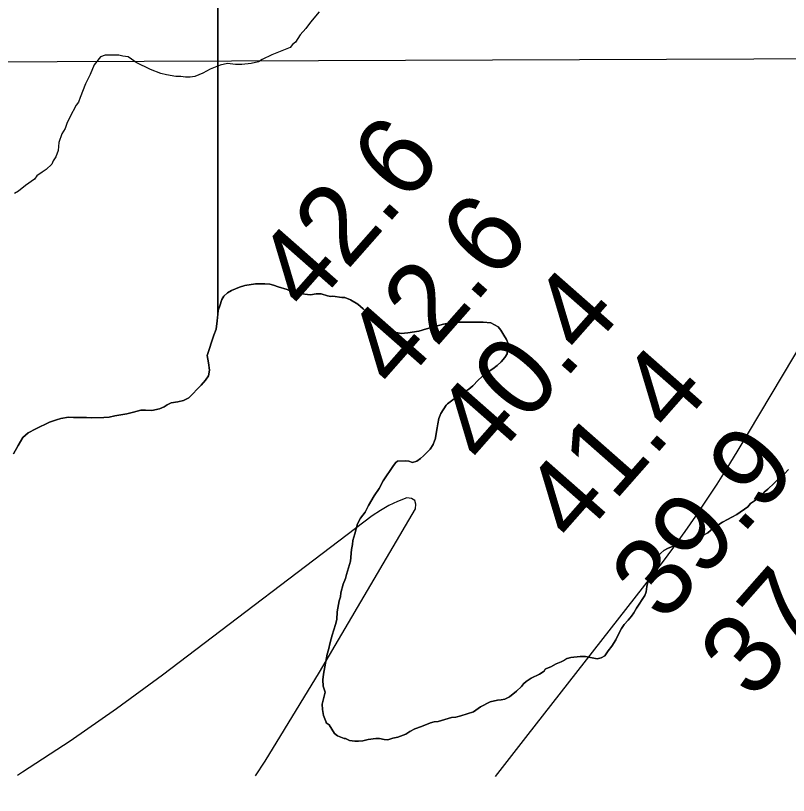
# Model space of a CAD drawing. Extents: x 3172297 to 3210190, y 958463 to 983887.
# Drawn here: x 3191237 to 3191893, y 963866 to 964528 of the extents above; entities that cross this region are included whole.
import ezdxf

# ---------------------------------------------------------------- set-up
doc = ezdxf.new("R2010")
doc.units = 0
for name, color, linetype in [('V-RIVR-RANG', 7, 'Continuous'), ('V-SITE-VEGE', 7, 'Continuous'), ('V-TOPO-BNDY', 7, 'Continuous'), ('V-TOPO-MAJR', 7, 'Continuous'), ('V-TOPO-SHOR', 7, 'Continuous'), ('V-WETL-SWMP', 7, 'Continuous')]:
    doc.layers.add(name, color=color, linetype=linetype)

msp = doc.modelspace()

# ---------------------------------------------------------------- linework, layer by layer
at = {"layer": 'V-SITE-VEGE'}
for p, q in [((3191409.01, 965103.6), (3191409.01, 964274.09)), ((3191409.01, 964274.09), (3191409.01, 965103.6)), ((3191427.47, 964297.52), (3191431.95, 964298.91)), ((3191431.95, 964298.91), (3191440.9, 964300.32)), ((3191440.9, 964300.32), (3191448.82, 964300.35)), ((3191448.82, 964300.35), (3191453.3, 964300.02)), ((3191453.3, 964300.02), (3191456.4, 964299.34)), ((3191456.4, 964299.34), (3191460.19, 964297.97)), ((3191414.06, 964289.9), (3191417.16, 964292.67)), ((3191417.16, 964292.67), (3191420.59, 964294.74)), ((3191420.59, 964294.74), (3191427.47, 964297.52)), ((3191460.19, 964297.97), (3191467.78, 964295.59)), ((3191467.78, 964295.59), (3191470.88, 964293.88)), ((3191470.88, 964293.88), (3191474.33, 964292.85)), ((3191474.33, 964292.85), (3191477.78, 964292.17)), ((3191410.65, 964281.63), (3191412.35, 964287.14)), ((3191412.35, 964287.14), (3191414.06, 964289.9)), ((3191477.78, 964292.17), (3191487.77, 964291.18)), ((3191487.77, 964291.18), (3191492.59, 964291.88)), ((3191492.59, 964291.88), (3191496.72, 964291.89)), ((3191496.72, 964291.89), (3191502.24, 964290.19)), ((3191502.24, 964290.19), (3191505, 964289.51)), ((3191505, 964289.51), (3191506.72, 964289.86)), ((3191506.72, 964289.86), (3191514.3, 964288.85)), ((3191514.3, 964288.85), (3191516.71, 964288.86)), ((3191516.71, 964288.86), (3191521.54, 964286.81)), ((3191521.54, 964286.81), (3191527.75, 964283.04)), ((3191409.28, 964277.83), (3191410.65, 964281.63)), ((3191527.75, 964283.04), (3191532.24, 964279.27)), ((3191532.24, 964279.27), (3191539.16, 964271.71)), ((3191408.62, 964268.87), (3191409.01, 964274.09)), ((3191409.01, 964274.09), (3191409.28, 964277.83)), ((3191407.61, 964261.98), (3191408.62, 964268.87)), ((3191539.16, 964271.71), (3191539.85, 964270.33)), ((3191539.85, 964270.33), (3191544.34, 964265.87)), ((3191544.34, 964265.87), (3191548.49, 964262.44)), ((3191586.03, 964262.22), (3191600.48, 964266.05)), ((3191600.48, 964266.05), (3191607.71, 964267.45)), ((3191607.71, 964267.45), (3191610.81, 964267.81)), ((3191610.81, 964267.81), (3191634.23, 964267.89)), ((3191634.23, 964267.89), (3191640.78, 964267.22)), ((3191640.78, 964267.22), (3191646.99, 964263.79)), ((3191405.56, 964256.81), (3191407.61, 964261.98)), ((3191548.49, 964262.44), (3191549.52, 964261.76)), ((3191549.52, 964261.76), (3191551.59, 964260.73)), ((3191551.59, 964260.73), (3191556.07, 964260.05)), ((3191556.07, 964260.05), (3191564.69, 964258.36)), ((3191570.2, 964258.72), (3191579.49, 964260.13)), ((3191579.49, 964260.13), (3191586.03, 964262.22)), ((3191646.99, 964263.79), (3191649.07, 964261.04)), ((3191649.07, 964261.04), (3191651.84, 964256.92)), ((3191400.1, 964239.57), (3191405.56, 964256.81)), ((3191564.69, 964258.36), (3191570.2, 964258.72)), ((3191651.84, 964256.92), (3191653.92, 964253.14)), ((3191653.92, 964253.14), (3191655.31, 964249.7)), ((3191655.31, 964249.7), (3191654.65, 964241.08)), ((3191401.16, 964233.37), (3191400.1, 964239.57)), ((3191654.65, 964241.08), (3191652.59, 964237.98)), ((3191401.87, 964227.17), (3191401.16, 964233.37)), ((3191649.5, 964234.18), (3191646.07, 964231.07)), ((3191652.59, 964237.98), (3191649.5, 964234.18)), ((3191401.19, 964222.35), (3191401.87, 964227.17)), ((3191642.29, 964228.3), (3191636.1, 964224.15)), ((3191646.07, 964231.07), (3191642.29, 964228.3)), ((3191398.45, 964218.55), (3191401.19, 964222.35)), ((3191636.1, 964224.15), (3191629.92, 964218.61)), ((3191384.38, 964203.7), (3191395.02, 964214.41)), ((3191395.02, 964214.41), (3191398.45, 964218.55)), ((3191625.46, 964213.78), (3191622.02, 964211.01)), ((3191629.92, 964218.61), (3191625.46, 964213.78)), ((3191614.11, 964206.16), (3191603.8, 964198.55)), ((3191616.86, 964207.55), (3191614.11, 964206.16)), ((3191622.02, 964211.01), (3191616.86, 964207.55)), ((3191369.58, 964199.51), (3191375.09, 964200.22)), ((3191375.09, 964200.22), (3191379.91, 964201.27)), ((3191379.91, 964201.27), (3191384.38, 964203.7)), ((3191337.57, 964191.49), (3191343.77, 964193.23)), ((3191343.77, 964193.23), (3191347.56, 964193.24)), ((3191347.56, 964193.24), (3191353.07, 964192.92)), ((3191353.07, 964192.92), (3191359.61, 964194.32)), ((3191359.61, 964194.32), (3191363.39, 964196.05)), ((3191363.39, 964196.05), (3191366.14, 964197.78)), ((3191366.14, 964197.78), (3191369.58, 964199.51)), ((3191602.77, 964197.52), (3191598.32, 964190.27)), ((3191603.8, 964198.55), (3191602.77, 964197.52)), ((3191275.94, 964186.12), (3191282.48, 964187.17)), ((3191282.48, 964187.17), (3191286.61, 964186.85)), ((3191286.61, 964186.85), (3191297.63, 964186.88)), ((3191297.63, 964186.88), (3191301.77, 964186.55)), ((3191301.77, 964186.55), (3191312.44, 964186.93)), ((3191312.44, 964186.93), (3191316.92, 964187.29)), ((3191316.92, 964187.29), (3191321.74, 964188.34)), ((3191321.74, 964188.34), (3191331.72, 964190.09)), ((3191331.72, 964190.09), (3191337.57, 964191.49)), ((3191598.32, 964190.27), (3191596.61, 964186.13)), ((3191254.61, 964177.44), (3191266.3, 964182.99)), ((3191266.3, 964182.99), (3191272.15, 964185.08)), ((3191272.15, 964185.08), (3191275.94, 964186.12)), ((3191595.59, 964181.65), (3191595.26, 964178.2)), ((3191596.61, 964186.13), (3191595.59, 964181.65)), ((3191243.61, 964169.83), (3191248.07, 964173.97)), ((3191248.07, 964173.97), (3191254.61, 964177.44)), ((3191595.26, 964178.2), (3191593.57, 964168.21)), ((3191239.5, 964163.27), (3191243.61, 964169.83)), ((3191593.23, 964167.86), (3191591.86, 964164.07)), ((3191593.57, 964168.21), (3191593.23, 964167.86)), ((3191235.73, 964156.02), (3191239.5, 964163.27)), ((3191589.12, 964159.93), (3191583.63, 964154.4)), ((3191591.86, 964164.07), (3191589.12, 964159.93)), ((3191583.63, 964154.4), (3191580.88, 964151.98)), ((3191560.22, 964148.81), (3191558.16, 964146.05)), ((3191561.6, 964149.85), (3191560.22, 964148.81)), ((3191568.14, 964150.21), (3191561.6, 964149.85)), ((3191571.24, 964149.88), (3191568.14, 964150.21)), ((3191574.35, 964148.86), (3191571.24, 964149.88)), ((3191577.79, 964149.9), (3191574.35, 964148.86)), ((3191580.88, 964151.98), (3191577.79, 964149.9)), ((3191558.16, 964146.05), (3191549.25, 964133.28)), ((3191889.54, 964138.86), (3191893.32, 964142.66)), ((3191880.96, 964131.25), (3191885.42, 964135.4)), ((3191885.42, 964135.4), (3191889.54, 964138.86)), ((3191545.83, 964126.72), (3191541.71, 964120.51)), ((3191549.25, 964133.28), (3191545.83, 964126.72)), ((3191875.8, 964126.07), (3191880.96, 964131.25)), ((3191541.71, 964120.51), (3191536.92, 964112.23)), ((3191865.16, 964116.73), (3191872.71, 964123.65)), ((3191872.71, 964123.65), (3191875.8, 964126.07)), ((3191858.63, 964111.2), (3191861.03, 964113.97)), ((3191861.03, 964113.97), (3191865.16, 964116.73)), ((3191536.92, 964112.23), (3191534.18, 964106.7)), ((3191849.35, 964104.63), (3191858.63, 964111.2)), ((3191530.06, 964101.53), (3191527.67, 964096.7)), ((3191534.18, 964106.7), (3191530.06, 964101.53)), ((3191837.32, 964098.05), (3191841.45, 964100.47)), ((3191841.45, 964100.47), (3191845.23, 964102.21)), ((3191845.23, 964102.21), (3191849.35, 964104.63)), ((3191527.67, 964096.7), (3191525.29, 964088.08)), ((3191829.41, 964092.85), (3191837.32, 964098.05)), ((3191525.29, 964088.08), (3191523.58, 964082.56)), ((3191820.48, 964086.62), (3191824.95, 964089.05)), ((3191824.95, 964089.05), (3191829.41, 964092.85)), ((3191523.58, 964082.56), (3191523.25, 964079.11)), ((3191790.55, 964075.85), (3191802.93, 964080.71)), ((3191802.93, 964080.71), (3191805.68, 964082.1)), ((3191805.68, 964082.1), (3191809.47, 964083.14)), ((3191809.47, 964083.14), (3191820.48, 964086.62)), ((3191522.58, 964074.98), (3191521.57, 964064.99)), ((3191523.25, 964079.11), (3191522.58, 964074.98)), ((3191782.3, 964069.62), (3191787.45, 964074.12)), ((3191787.45, 964074.12), (3191790.55, 964075.85)), ((3191780.25, 964064.79), (3191780.93, 964067.55)), ((3191780.93, 964067.55), (3191782.3, 964069.62)), ((3191521.57, 964064.99), (3191518.16, 964053.61)), ((3191779.58, 964059.97), (3191780.25, 964064.79)), ((3191775.12, 964051.69), (3191776.5, 964054.45)), ((3191776.5, 964054.45), (3191779.58, 964059.97)), ((3191517.49, 964050.16), (3191515.44, 964045.33)), ((3191518.16, 964053.61), (3191517.49, 964050.16)), ((3191773.08, 964043.42), (3191775.12, 964051.69)), ((3191515.44, 964045.33), (3191513.39, 964038.09)), ((3191772.41, 964038.93), (3191773.08, 964043.42)), ((3191513.06, 964034.65), (3191512.04, 964031.2)), ((3191513.39, 964038.09), (3191513.06, 964034.65)), ((3191764.19, 964025.13), (3191771.39, 964035.83)), ((3191771.39, 964035.83), (3191772.41, 964038.93)), ((3191511.36, 964028.1), (3191510.35, 964021.9)), ((3191512.04, 964031.2), (3191511.36, 964028.1)), ((3191510.35, 964021.9), (3191510.02, 964015.35)), ((3191760.08, 964018.23), (3191762.14, 964020.99)), ((3191762.14, 964020.99), (3191764.19, 964025.13)), ((3191510.02, 964015.35), (3191509, 964011.21)), ((3191753.9, 964011.32), (3191757.33, 964014.78)), ((3191757.33, 964014.78), (3191760.08, 964018.23)), ((3191509, 964011.21), (3191505.93, 964002.25)), ((3191749.45, 964004.07), (3191751.5, 964007.87)), ((3191751.5, 964007.87), (3191753.9, 964011.32)), ((3191505.93, 964002.25), (3191504.23, 963996.04)), ((3191746.71, 963998.21), (3191749.45, 964004.07)), ((3191504.23, 963996.04), (3191502.87, 963989.84)), ((3191743.28, 963992.69), (3191746.71, 963998.21)), ((3191502.87, 963989.84), (3191501.85, 963986.04)), ((3191737.45, 963984.74), (3191740.2, 963988.89)), ((3191740.2, 963988.89), (3191743.28, 963992.69)), ((3191501.85, 963986.04), (3191498.81, 963969.16)), ((3191700.27, 963979.46), (3191705.43, 963982.23)), ((3191705.43, 963982.23), (3191708.53, 963983.27)), ((3191708.53, 963983.27), (3191716.45, 963983.99)), ((3191716.45, 963983.99), (3191720.92, 963984)), ((3191720.92, 963984), (3191730.92, 963981.97)), ((3191730.92, 963981.97), (3191734.36, 963983.01)), ((3191734.36, 963983.01), (3191737.45, 963984.74)), ((3191687.89, 963973.91), (3191691.68, 963975.29)), ((3191691.68, 963975.29), (3191696.14, 963977.72)), ((3191696.14, 963977.72), (3191700.27, 963979.46)), ((3191498.81, 963969.16), (3191498.13, 963964.33)), ((3191674.83, 963965.59), (3191682.05, 963969.06)), ((3191682.05, 963969.06), (3191685.83, 963971.49)), ((3191685.83, 963971.49), (3191686.86, 963973.21)), ((3191686.86, 963973.21), (3191687.89, 963973.91)), ((3191498.13, 963964.33), (3191498.5, 963958.82)), ((3191668.3, 963960.75), (3191670.7, 963962.83)), ((3191670.7, 963962.83), (3191674.83, 963965.59)), ((3191498.5, 963958.82), (3191500.23, 963953.66)), ((3191662.46, 963954.53), (3191666.58, 963958.68)), ((3191666.58, 963958.68), (3191668.3, 963960.75)), ((3191500.23, 963953.66), (3191497.51, 963943.67)), ((3191652.5, 963947.96), (3191656.62, 963949.69)), ((3191656.62, 963949.69), (3191662.46, 963954.53)), ((3191497.51, 963943.67), (3191497.87, 963939.18)), ((3191631.85, 963941.34), (3191640.1, 963945.5)), ((3191640.1, 963945.5), (3191646.3, 963946.9)), ((3191646.3, 963946.9), (3191649.4, 963947.26)), ((3191649.4, 963947.26), (3191652.5, 963947.96)), ((3191497.87, 963939.18), (3191498.58, 963934.02)), ((3191615.34, 963933.71), (3191626.01, 963937.19)), ((3191626.01, 963937.19), (3191631.85, 963941.34)), ((3191498.58, 963934.02), (3191501.01, 963928.18)), ((3191501.01, 963928.18), (3191501.01, 963927.83)), ((3191589.53, 963927.78), (3191592.62, 963928.47)), ((3191592.62, 963928.47), (3191596.07, 963928.83)), ((3191596.07, 963928.83), (3191607.43, 963932.31)), ((3191607.43, 963932.31), (3191610.87, 963932.66)), ((3191610.87, 963932.66), (3191615.34, 963933.71)), ((3191501.01, 963927.83), (3191503.42, 963926.12)), ((3191503.42, 963926.12), (3191507.93, 963918.55)), ((3191571.99, 963920.48), (3191576.11, 963922.56)), ((3191576.11, 963922.56), (3191581.96, 963924.65)), ((3191581.96, 963924.65), (3191589.53, 963927.78)), ((3191507.93, 963918.55), (3191510.69, 963916.84)), ((3191510.69, 963916.84), (3191516.21, 963914.45)), ((3191557.54, 963914.58), (3191561.67, 963915.63)), ((3191561.67, 963915.63), (3191568.55, 963918.06)), ((3191568.55, 963918.06), (3191571.99, 963920.48)), ((3191516.21, 963914.45), (3191517.24, 963914.45)), ((3191517.24, 963914.45), (3191520.69, 963912.74)), ((3191520.69, 963912.74), (3191525.17, 963912.06)), ((3191525.17, 963912.06), (3191528.27, 963912.08)), ((3191528.27, 963912.08), (3191532.06, 963912.43)), ((3191532.06, 963912.43), (3191536.53, 963913.48)), ((3191536.53, 963913.48), (3191543.07, 963914.53)), ((3191543.07, 963914.53), (3191546.17, 963914.55)), ((3191546.17, 963914.55), (3191550.31, 963913.53)), ((3191550.31, 963913.53), (3191553.41, 963913.19)), ((3191553.41, 963913.19), (3191557.54, 963914.58))]:
    msp.add_line(p, q, dxfattribs=at)
at = {"layer": 'V-TOPO-BNDY'}
msp.add_lwpolyline([(3186048.77, 963895.97), (3186249.57, 964469.98), (3198733.3, 964517.56), (3198114.71, 963866.13)], dxfattribs=at)
at = {"layer": 'V-TOPO-MAJR'}
for points in [[(3191992.73, 964398.26), (3191849.44, 964157.8), (3191841.01, 964143.98), (3191832.41, 964130.26), (3191823.54, 964116.72), (3191814.49, 964103.29), (3191805.19, 964090.03), (3191795.73, 964076.89), (3191786.03, 964063.92), (3191776.19, 964051.07), (3191672.07, 963917.7), (3191644.33, 963882.13)], [(3191441.15, 963882.63), (3191449.22, 963895.21), (3191495.4, 963970.82), (3191576.81, 964109.29), (3191577.19, 964113.41), (3191576.29, 964116.51), (3191573.46, 964118.07), (3191569.35, 964118.6), (3191561.58, 964115.65), (3191554.07, 964112.22), (3191546.95, 964108.04), (3191540.09, 964103.36), (3191362.1, 963968.3), (3191323.2, 963939.76), (3191283.71, 963912.09), (3191243.35, 963885.72), (3191239.19, 963883.13)]]:
    msp.add_lwpolyline(points, dxfattribs=at)
at = {"layer": 'V-TOPO-SHOR'}
for points in [[(3191622.02, 964211.01), (3191625.46, 964213.78), (3191629.92, 964218.61), (3191636.1, 964224.15), (3191642.29, 964228.3), (3191646.07, 964231.07), (3191649.5, 964234.18), (3191652.59, 964237.98), (3191654.65, 964241.08), (3191655.3, 964249.7), (3191653.92, 964253.14), (3191651.84, 964256.92), (3191649.07, 964261.04), (3191646.99, 964263.79), (3191640.78, 964267.22), (3191634.23, 964267.89), (3191610.81, 964267.81), (3191607.71, 964267.45), (3191600.48, 964266.05), (3191586.03, 964262.22), (3191579.49, 964260.13), (3191570.2, 964258.72), (3191564.69, 964258.36), (3191556.07, 964260.05), (3191551.59, 964260.73), (3191549.52, 964261.75), (3191548.49, 964262.44), (3191544.34, 964265.87), (3191539.85, 964270.33), (3191539.16, 964271.71), (3191532.24, 964279.27), (3191527.75, 964283.04), (3191521.54, 964286.81), (3191516.71, 964288.86), (3191514.3, 964288.85), (3191506.72, 964289.86), (3191505, 964289.51), (3191502.24, 964290.19), (3191496.72, 964291.89), (3191492.59, 964291.88), (3191487.77, 964291.18), (3191477.78, 964292.17), (3191474.33, 964292.85), (3191470.88, 964293.88), (3191467.78, 964295.59), (3191460.19, 964297.97), (3191456.4, 964299.34), (3191453.3, 964300.02), (3191448.82, 964300.35), (3191440.9, 964300.32), (3191431.95, 964298.91), (3191427.47, 964297.52), (3191420.59, 964294.74), (3191417.16, 964292.67), (3191414.06, 964289.9), (3191412.35, 964287.14), (3191410.65, 964281.63), (3191409.28, 964277.83), (3191408.62, 964268.87), (3191407.61, 964261.98), (3191405.56, 964256.81), (3191400.1, 964239.57), (3191401.16, 964233.37), (3191401.87, 964227.17), (3191401.19, 964222.35), (3191398.45, 964218.55), (3191395.02, 964214.41), (3191384.38, 964203.7), (3191379.91, 964201.27), (3191375.09, 964200.22), (3191369.58, 964199.51), (3191366.14, 964197.78), (3191363.39, 964196.05), (3191359.61, 964194.32), (3191353.07, 964192.92), (3191347.56, 964193.24), (3191343.77, 964193.23), (3191337.57, 964191.49), (3191331.72, 964190.09), (3191321.74, 964188.33), (3191316.92, 964187.29), (3191312.44, 964186.93), (3191301.77, 964186.55), (3191297.63, 964186.88), (3191286.61, 964186.84), (3191282.48, 964187.17), (3191275.94, 964186.12), (3191272.15, 964185.08), (3191266.3, 964182.99), (3191254.61, 964177.44), (3191248.07, 964173.97), (3191243.61, 964169.83), (3191239.5, 964163.27), (3191235.73, 964156.02)], [(3191696.14, 963977.72), (3191691.68, 963975.29), (3191687.89, 963973.91), (3191686.86, 963973.21), (3191685.83, 963971.49), (3191682.05, 963969.06), (3191674.83, 963965.59), (3191670.7, 963962.83), (3191668.3, 963960.75), (3191666.58, 963958.68), (3191662.46, 963954.53), (3191656.62, 963949.69), (3191652.5, 963947.96), (3191649.4, 963947.26), (3191646.3, 963946.9), (3191640.1, 963945.5), (3191631.85, 963941.34), (3191626.01, 963937.19), (3191615.34, 963933.71), (3191610.87, 963932.66), (3191607.43, 963932.31), (3191596.07, 963928.83), (3191592.62, 963928.47), (3191589.53, 963927.78), (3191581.96, 963924.65), (3191576.11, 963922.56), (3191571.98, 963920.48), (3191568.55, 963918.06), (3191561.67, 963915.63), (3191557.54, 963914.58), (3191553.41, 963913.19), (3191550.31, 963913.53), (3191546.17, 963914.55), (3191543.07, 963914.53), (3191536.53, 963913.48), (3191532.06, 963912.43), (3191528.27, 963912.08), (3191525.17, 963912.06), (3191520.69, 963912.74), (3191517.24, 963914.45), (3191516.21, 963914.45), (3191510.69, 963916.84), (3191507.93, 963918.55), (3191503.42, 963926.12), (3191501.01, 963927.83), (3191501.01, 963928.18), (3191498.58, 963934.02), (3191497.87, 963939.19), (3191497.51, 963943.67), (3191500.23, 963953.66), (3191498.5, 963958.82), (3191498.13, 963964.33), (3191498.81, 963969.16), (3191501.85, 963986.04), (3191502.87, 963989.84), (3191504.23, 963996.04), (3191505.93, 964002.25), (3191509, 964011.21), (3191510.02, 964015.35), (3191510.35, 964021.9), (3191511.36, 964028.1), (3191512.04, 964031.2), (3191513.06, 964034.65), (3191513.39, 964038.09), (3191515.44, 964045.33), (3191517.49, 964050.16), (3191518.16, 964053.61), (3191521.57, 964064.99), (3191522.57, 964074.98), (3191523.25, 964079.11), (3191523.58, 964082.56), (3191525.29, 964088.08), (3191527.67, 964096.7), (3191530.06, 964101.53), (3191534.18, 964106.7), (3191536.92, 964112.23), (3191541.71, 964120.51), (3191545.83, 964126.72), (3191549.25, 964133.28), (3191558.16, 964146.05), (3191560.22, 964148.81), (3191561.6, 964149.85), (3191568.14, 964150.21), (3191571.24, 964149.88), (3191574.35, 964148.86), (3191577.79, 964149.9), (3191580.88, 964151.98), (3191583.63, 964154.4), (3191589.12, 964159.93), (3191591.86, 964164.07), (3191593.23, 964167.86), (3191593.57, 964168.21), (3191595.26, 964178.2), (3191595.59, 964181.65), (3191596.61, 964186.13), (3191598.32, 964190.27), (3191602.77, 964197.52), (3191603.8, 964198.55), (3191614.11, 964206.16), (3191616.86, 964207.55), (3191622.02, 964211.01)], [(3191893.32, 964142.66), (3191889.54, 964138.86), (3191885.42, 964135.4), (3191880.96, 964131.25), (3191875.8, 964126.07), (3191872.71, 964123.65), (3191865.16, 964116.73), (3191861.03, 964113.97), (3191858.63, 964111.2), (3191849.35, 964104.63), (3191845.23, 964102.21), (3191841.45, 964100.47), (3191837.32, 964098.05), (3191829.41, 964092.85), (3191824.95, 964089.05), (3191820.48, 964086.62), (3191809.47, 964083.14), (3191805.68, 964082.1), (3191802.93, 964080.71), (3191790.55, 964075.85), (3191787.45, 964074.12), (3191782.3, 964069.62), (3191780.93, 964067.55), (3191780.25, 964064.79), (3191779.58, 964059.97), (3191776.5, 964054.45), (3191775.12, 964051.69), (3191773.08, 964043.42), (3191772.41, 964038.94), (3191771.39, 964035.83), (3191764.19, 964025.13), (3191762.14, 964020.99), (3191760.08, 964018.23), (3191757.33, 964014.78), (3191753.9, 964011.32), (3191751.5, 964007.87), (3191749.45, 964004.07), (3191746.71, 963998.21), (3191743.28, 963992.69), (3191740.2, 963988.89), (3191737.45, 963984.74), (3191734.36, 963983.01), (3191730.92, 963981.97), (3191720.92, 963984), (3191716.45, 963983.99), (3191708.53, 963983.27), (3191705.43, 963982.23), (3191702.33, 963980.5), (3191700.27, 963979.46), (3191696.14, 963977.72)]]:
    msp.add_lwpolyline(points, dxfattribs=at)
at = {"layer": 'V-WETL-SWMP'}
for points in [[(3191495.12, 964531.3), (3191487.75, 964522.53), (3191483.73, 964517.13), (3191479.04, 964511.73), (3191475.02, 964505.66), (3191472.34, 964503.64), (3191470.33, 964500.94), (3191454.87, 964494.83), (3191446.81, 964490.77), (3191443.46, 964488.74), (3191437.41, 964487.38), (3191429.33, 964486.68), (3191423.95, 964486.66), (3191417.22, 964487.31), (3191411.17, 964485.95), (3191402.44, 964482.55), (3191396.39, 964479.17), (3191389.67, 964476.46), (3191385.64, 964475.77), (3191381.6, 964475.76), (3191377.56, 964476.42), (3191373.52, 964476.4), (3191365.45, 964477.72), (3191360.73, 964479.05), (3191351.98, 964482.39), (3191339.85, 964488.4), (3191335.8, 964491.08), (3191333.1, 964493.09), (3191328.39, 964493.75), (3191325.02, 964494.41), (3191313.59, 964494.37), (3191309.55, 964493.02), (3191304.19, 964486.27), (3191300.86, 964478.19), (3191296.85, 964470.1), (3191292.17, 964458.65), (3191290.84, 964454.6), (3191288.83, 964451.91), (3191283.48, 964441.8), (3191280.81, 964436.41), (3191279.48, 964432.36), (3191276.8, 964427.65), (3191274.13, 964420.24), (3191273.48, 964413.51), (3191271.48, 964408.12), (3191269.47, 964404.75), (3191268.14, 964402.05), (3191263.44, 964397.33), (3191260.08, 964395.3), (3191255.39, 964391.92), (3191253.38, 964389.22), (3191245.99, 964383.81)], [(3191245.99, 964383.81), (3191239.95, 964379.08), (3191236.6, 964377.06)]]:
    msp.add_lwpolyline(points, dxfattribs=at)

# ---------------------------------------------------------------- texts
at = {"layer": 'V-RIVR-RANG'}
for s, p in [('42.6', (3191485.66, 964273.85)), ('42.6', (3191560.86, 964207.94)), ('40.4', (3191637.29, 964143.42)), ('41.4', (3191712.5, 964077.51)), ('39.9', (3191787.53, 964011.4)), ('37.5', (3191862.91, 963945.69))]:
    msp.add_text(s, height=67, rotation=48.62833, dxfattribs=at).set_placement(p)

doc.saveas('drawing.dxf')
